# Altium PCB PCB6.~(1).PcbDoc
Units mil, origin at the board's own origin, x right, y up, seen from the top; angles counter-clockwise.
Board outline 6000 x 4000 mil, 2 copper layers (Top Layer, Bottom Layer); 86 components, 57 nets, 223 pads, 27 vias.
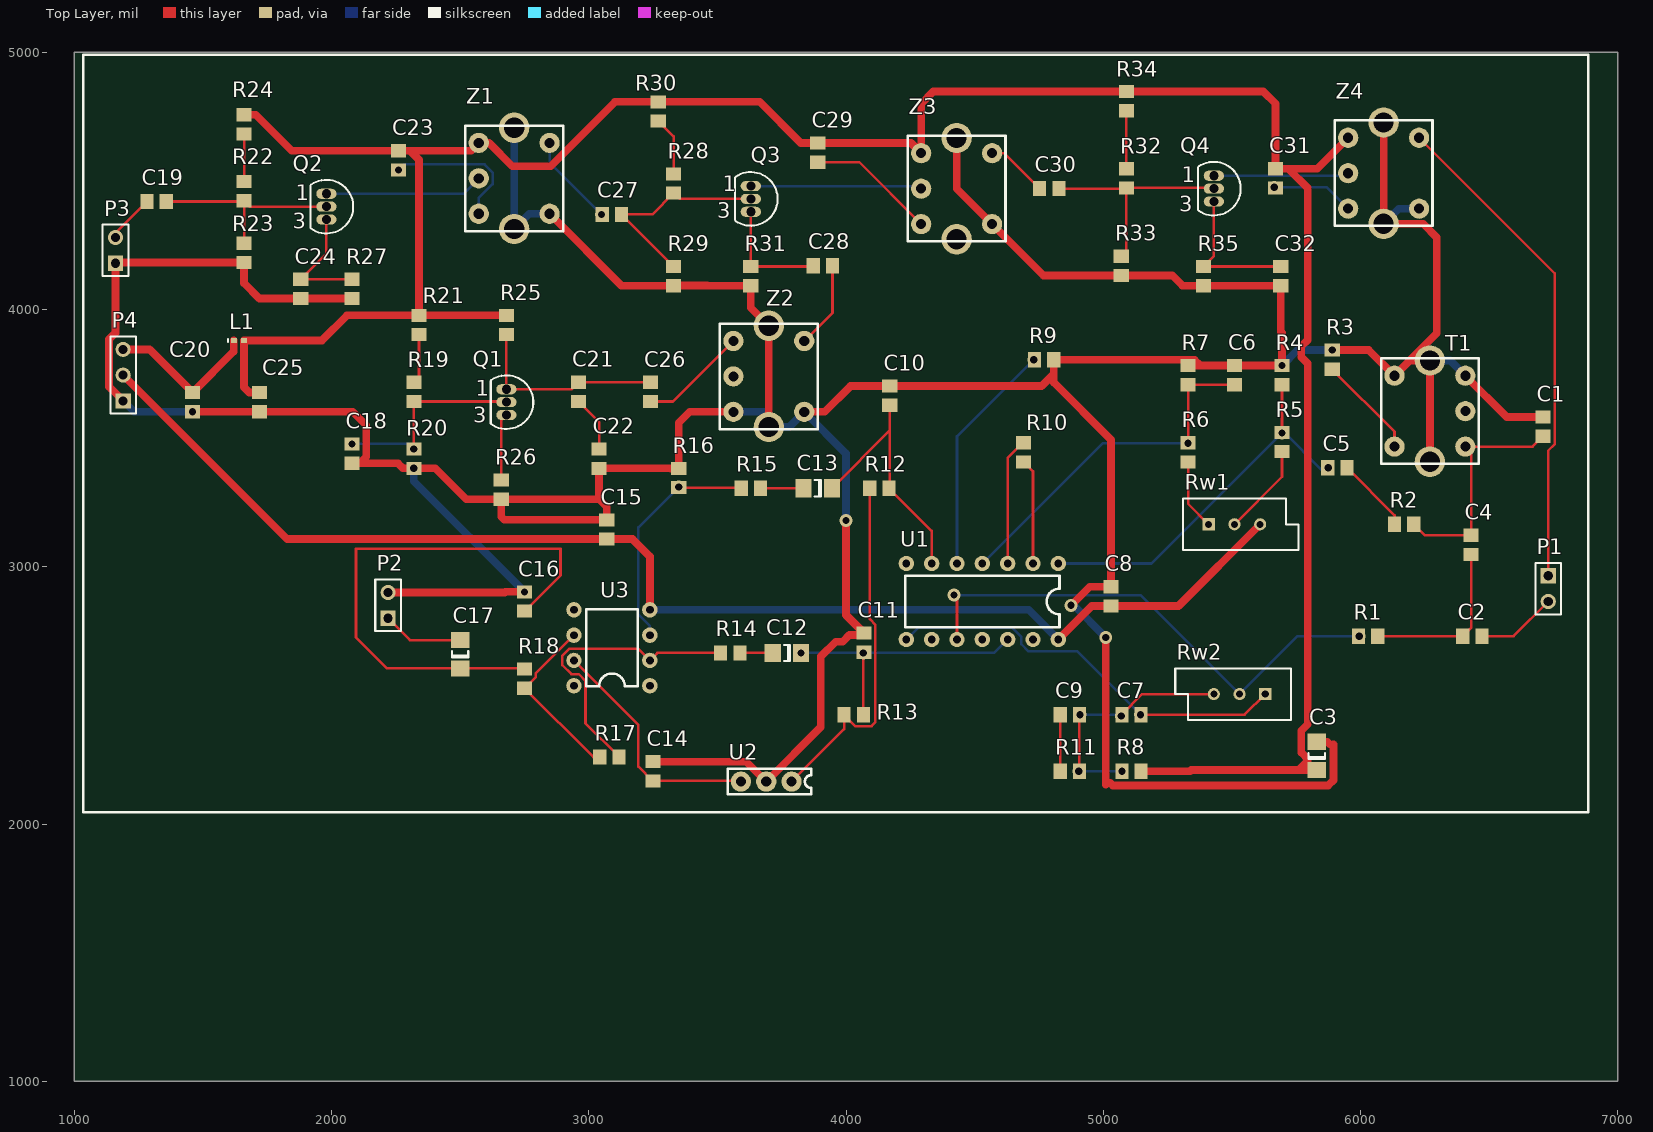
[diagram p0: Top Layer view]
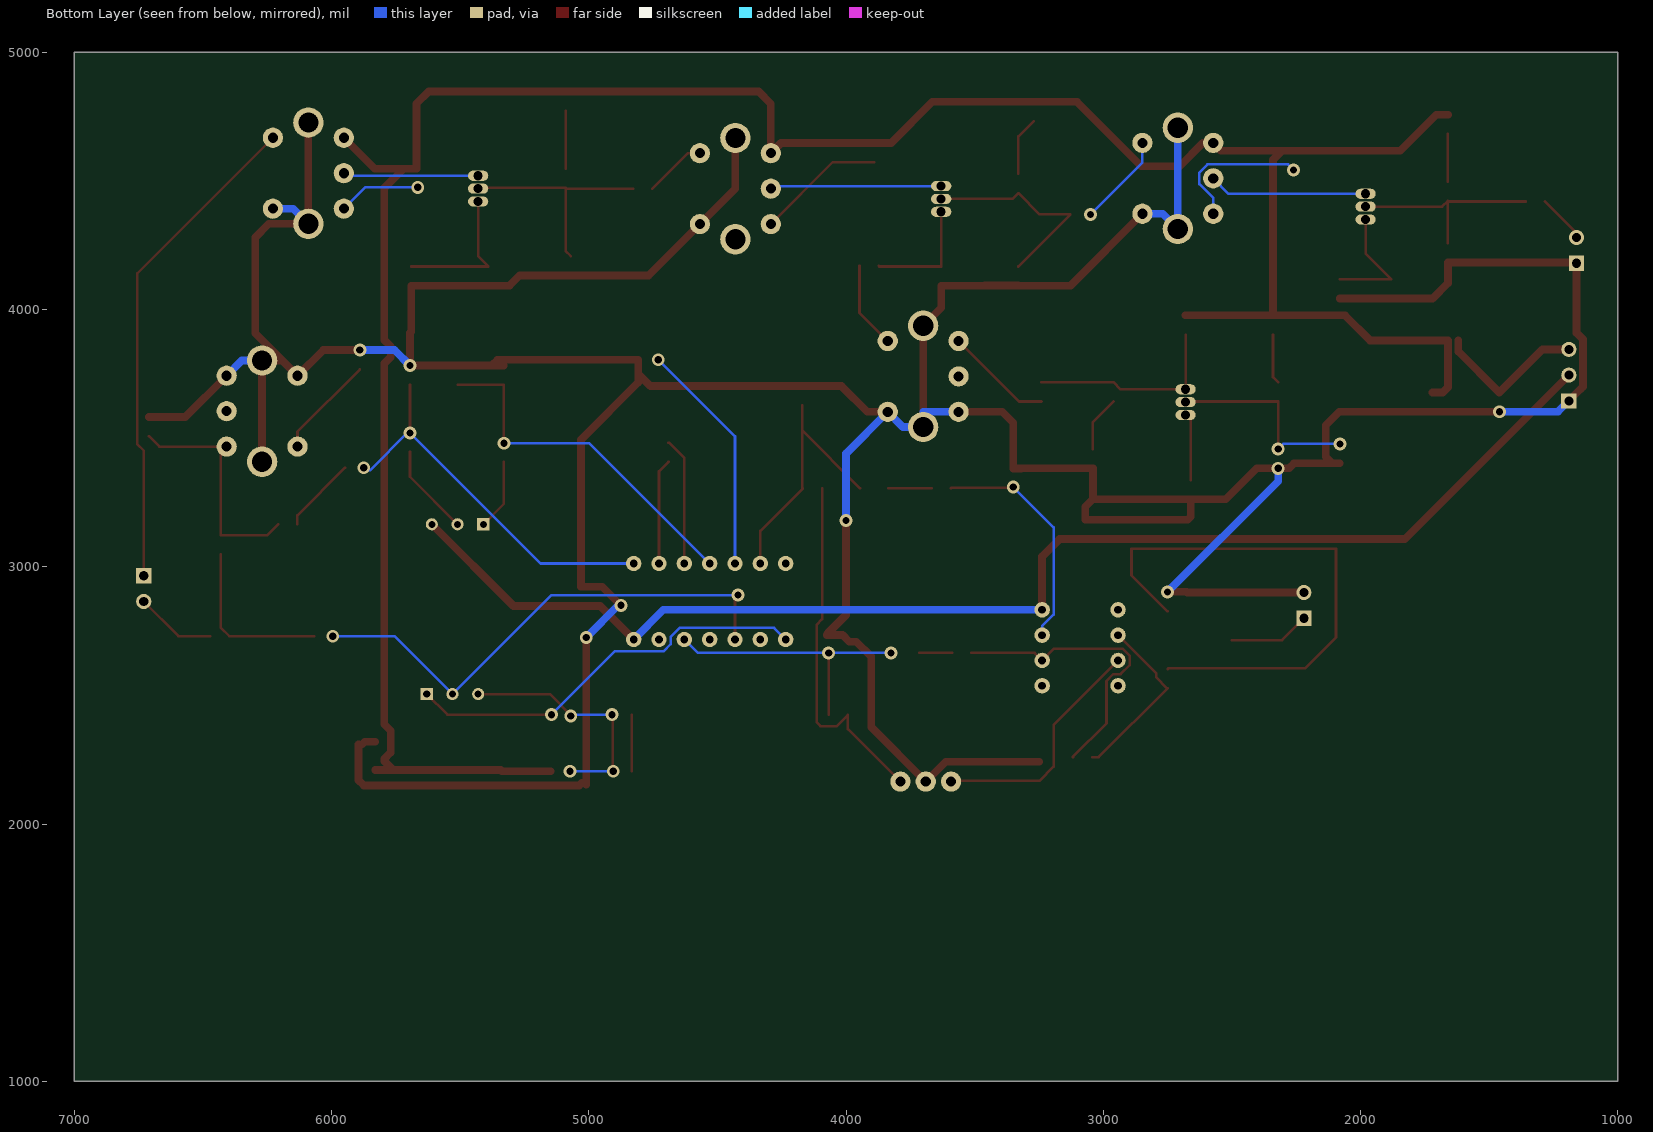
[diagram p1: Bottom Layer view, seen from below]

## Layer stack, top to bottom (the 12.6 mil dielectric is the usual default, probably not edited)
Top Layer: signal copper 1.4
Dielectric: dielectric 12.6, FR-4, Dk 4.8
Bottom Layer: signal copper 1.4

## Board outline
1000,1000 7000,1000 7000,5000 1000,5000

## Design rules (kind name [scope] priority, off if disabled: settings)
Clearance [All] p1: gap=10
PolygonConnect [All] p1: connectstyle=Relief reliefconductorwidth=10 reliefentries=4 polygonreliefangle="90 Angle"
RoutingVias [All] p1: holewidth=28 width=50 viastyle="Through Hole" minholewidth=28 minwidth=50 maxholewidth=28 maxwidth=50
SilkscreenOverComponentPads [All] p1: minsilkscreentomaskgap=10
SolderMaskExpansion [All] p1: expansion=4
TestPointUsage [All] p1: valid=0 allowmultiple=FALSE
Testpoint [All] p1: side=15 testpointundercomponent=TRUE minsize=40 maxsize=100 preferedsize=60 minholesize=0 maxholesize=40 preferedholesize=32 testpointgrid=1 style=1023 order=0123456789
Width [All] p1: maxlimit=100 minlimit=10 preferedwidth=10 minimp=50.000000 maximp=50.000000 favimp=50.000000
23 further rules are at their usual default settings.

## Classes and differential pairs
component class Sheet2: C18 C19 C20 C21 C22 C23 C24 C25 C26 C27 C28 C29 C30 C31 C32 L1 P3 P4 Q1 Q2 Q3 Q4 R19 R20 R21 R22 R23 R24 R25 R26 R27 R28 R29 R30 R31 R32 R33 R34 R35 Z1 Z2 Z3 Z4
component class Sheet1: C1 C2 C3 C4 C5 C6 C7 C8 C9 C10 C11 C12 C13 C14 C15 C16 C17 P1 P2 R1 R2 R3 R4 R5 R6 R7 R8 R9 R10 R11 R12 R13 R14 R15 R16 R17 R18 Rw1 Rw2 T1 U1 U2 U3

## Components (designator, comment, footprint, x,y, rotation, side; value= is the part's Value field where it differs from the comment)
C1 "Cap" 2012[0805] 6710,3545 r270 top
C2 "Cap" 2012[0805] 6435,2730 r180 top
C3 "Cap Pol1" C1206 5830,2265 r90 top
C4 "Cap" 2012[0805] 6430,3085 r270 top
C5 "Cap" 2012[0805] 5910,3385 r180 top
C6 "Cap" 2012[0805] 5510,3745 r270 top
C7 "Cap" 2012[0805] 5110,2425 r180 top
C8 "Cap" 2012[0805] 5030,2885 r270 top
C9 "Cap" 2012[0805] 4870,2425 r180 top
C10 "Cap" 2012[0805] 4170,3665 r270 top
C11 "Cap" 2012[0805] 4070,2705 r270 top
C12 "Cap Pol1" C1206 3770,2665 r180 top
C13 "Cap Pol1" C1206 3890,3305 r180 top
C14 "Cap" 2012[0805] 3250,2205 r270 top
C15 "Cap" 2012[0805] 3070,3145 r270 top
C16 "Cap" 2012[0805] 2750,2865 r270 top
C17 "Cap Pol1" C1206 2500,2660 r90 top
C18 "Cap" 2012[0805] 2080,3440 r270 top
C19 "Cap" 2012[0805] 1320,4420 r0 top
C20 "Cap" 2012[0805] 1460,3640 r90 top
C21 "Cap" 2012[0805] 2960,3680 r270 top
C22 "Cap" 2012[0805] 3040,3420 r270 top
C23 "Cap" 2012[0805] 2260,4580 r270 top
C24 "Cap" 2012[0805] 1880,4080 r90 top
C25 "Cap" 2012[0805] 1720,3640 r90 top
C26 "Cap" 2012[0805] 3240,3680 r90 top
C27 "Cap" 2012[0805] 3090,4370 r0 top
C28 "Cap" 2012[0805] 3910,4170 r0 top
C29 "Cap" 2012[0805] 3890,4610 r270 top
C30 "Cap" 2012[0805] 4790,4470 r0 top
C31 "Cap" 2012[0805] 5670,4510 r270 top
C32 "Cap" 2012[0805] 5690,4130 r90 top
L1 "Inductor" 0402-A 1640,3880 r0 top
P1 "Header 2" HDR1X2 6730,2965 r270 top
P2 "Header 2" HDR1X2 2220,2800 r90 top
P3 "Header 2" HDR1X2 1160,4180 r90 top
P4 "Header 3" HDR1X3 1190,3645 r90 top
Q1 "NPN" TO-226 2680,3640 r180 top
Q2 "NPN" TO-226 1980,4400 r180 top
Q3 "NPN" TO-226 3630,4430 r180 top
Q4 "NPN" TO-226 5430,4470 r180 top
R1 "Res1" 2012[0805] 6030,2730 r180 top
R2 "Res1" 2012[0805] 6170,3165 r180 top
R3 "Res1" 2012[0805] 5890,3805 r270 top
R4 "Res1" 2012[0805] 5695,3745 r270 top
R5 "Res1" 2012[0805] 5695,3485 r270 top
R6 "Res1" 2012[0805] 5330,3445 r270 top
R7 "Res1" 2012[0805] 5330,3745 r270 top
R8 "Res1" 2012[0805] 5110,2205 r180 top
R9 "Res1" 2012[0805] 4770,3805 r180 top
R10 "Res1" 2012[0805] 4690,3445 r270 top
R11 "Res1" 2012[0805] 4870,2205 r180 top
R12 "Res1" 2012[0805] 4130,3305 r180 top
R13 "Res1" 2012[0805] 4030,2425 r180 top
R14 "Res1" 2012[0805] 3550,2665 r180 top
R15 "Res1" 2012[0805] 3630,3305 r180 top
R16 "Res1" 2012[0805] 3350,3345 r270 top
R17 "Res1" 2012[0805] 3080,2260 r180 top
R18 "Res1" 2012[0805] 2750,2565 r270 top
R19 "Res1" 2012[0805] 2320,3680 r90 top
R20 "Res1" 2012[0805] 2320,3420 r90 top
R21 "Res Adj1" 2012[0805] 2340,3940 r270 top
R22 "Res1" 2012[0805] 1660,4460 r90 top
R23 "Res1" 2012[0805] 1660,4220 r90 top
R24 "Res Adj1" 2012[0805] 1660,4720 r270 top
R25 "Res1" 2012[0805] 2680,3940 r90 top
R26 "Res1" 2012[0805] 2660,3300 r90 top
R27 "Res1" 2012[0805] 2080,4080 r90 top
R28 "Res1" 2012[0805] 3330,4490 r90 top
R29 "Res1" 2012[0805] 3330,4130 r90 top
R30 "Res Adj1" 2012[0805] 3270,4770 r270 top
R31 "Res1" 2012[0805] 3630,4130 r90 top
R32 "Res1" 2012[0805] 5090,4510 r90 top
R33 "Res1" 2012[0805] 5070,4170 r90 top
R34 "Res Adj1" 2012[0805] 5090,4810 r270 top
R35 "Res1" 2012[0805] 5390,4130 r90 top
Rw1 "RPot" VR5 5510,3165 r0 top
Rw2 "RPot" VR5 5530,2505 r180 top
T1 "zhongzhou" zhongzhou 6270,3605 r180 top
U1 "MC1496" MC1496 4530,2865 r180 top
U2 "LM7808" LM7808 3690,2165 r180 top
U3 "LM741" LM741 3090,2685 r180 top
Z1 "zhongzhou1" zhongzhou 2710,4510 r0 top
Z2 "zhongzhou4" zhongzhou 3700,3740 r0 top
Z3 "zhongzhou2" zhongzhou 4430,4470 r0 top
Z4 "zhongzhou3" zhongzhou 6090,4530 r0 top

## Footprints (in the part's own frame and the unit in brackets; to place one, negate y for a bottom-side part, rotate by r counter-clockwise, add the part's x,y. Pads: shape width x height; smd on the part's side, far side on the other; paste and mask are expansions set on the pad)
0402-A [mm] "Chip Inductor; Body 1 x 0.5 mm (LxW typ)"
  rect 0.6x0.5 smd: 1(-0.5,0) 2(0.5,0)
  silkscreen extent -1.1,-0.15 -1.1,0.15
2012[0805] [mm] "Chip Resistor; Body 2.0 x 1.3 mm (LxW typ)"
  rect 1.3x1.5 smd: 1(-0.95,0) 2(0.95,0)
C1206 [mm] "Chip Capacitor; Body 3.2 x 1.6 mm (LxW typ)"
  rect 1.6x1.8 smd: 1(-1.4,0) 2(1.4,0)
  silkscreen extent -0.3,-0.8 0.3,0.8
HDR1X2 [mm] "Connector; Header; 2 Position"
  rect 1.5x1.5 hole 0.9: 1(0,0)
  round 1.5 hole 0.9: 2(2.54,0)
  silkscreen extent -1.27,-1.27 3.81,1.27
HDR1X3 [mm] "Connector; Header; 3 Position"
  rect 1.5x1.5 hole 0.9: 1(0,0)
  round 1.5 hole 0.9: 2(2.54,0) 3(5.08,0)
  silkscreen extent -1.27,-1.27 6.35,1.27
LM741 [mil]
  round 60 hole 30: 1(-147.64,147.64) 2(-147.64,49.21) 3(-147.64,-49.21) 4(-147.64,-147.64) 5(147.64,-147.64) 6(147.64,-49.21) 7(147.64,49.21) 8(147.64,147.64)
  silkscreen extent -100,-150 100,150
LM7808 [mm]
  round 2 hole 1: 1(-2.5,0) 2(0,0) 3(2.5,0)
  silkscreen extent -4.44,-1.27 3.81,1.27
MC1496 [mil]
  round 60 hole 30: 1(-295.28,-147.64) 2(-196.85,-147.64) 3(-98.43,-147.64) 4(0,-147.64) 5(98.43,-147.64) 6(196.85,-147.64) 7(295.28,-147.64) 8(295.28,147.64) 9(196.85,147.64) 10(98.43,147.64) 11(0,147.64) 12(-98.43,147.64) 13(-196.85,147.64) 14(-295.28,147.64)
  silkscreen extent -300,-100 300,100
TO-226 [mm] "TO, Flat Index; 3 In-Line, Axial Leads; Body Dia. 4.8mm; Leads 0.55 x 0.51 mm (max)"
  oval 2x1 hole 0.9: 1(0,-1.27) 2(0,0) 3(0,1.27)
  silkscreen extent -2.65,-2.65 1.55,2.65
VR5 [mm] "Potentiometer; 3 Leads"
  rect 1.2x1.2 hole 0.7: 1(-2.54,0)
  round 1.2 hole 0.7: 2(0,0) 3(2.54,0)
  silkscreen extent -5.08,-2.54 6.35,2.54
zhongzhou [mm]
  round 2 hole 1: 1(-3.5,3.5) 2(-3.5,0) 3(-3.5,-3.5) 4(3.5,-3.5) 5(3.5,3.5)
  round 3 hole 2: 6(0,5) 7(0,-5)
  silkscreen extent -4.83,-5.21 4.83,5.21

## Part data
C1 C2 C4 C5 C6 C7 C8 C9 C10 C11 C14 C15 C16 C18 C19 C20 C21 C22 C23 C24 C25 C26 C27 C28 C29 C30 C31 C32: "Capacitor"
C3 C12 C13 C17: "Polarized Capacitor (Radial)"
P1 P2 P3: "Header, 2-Pin"
P4: "Header, 3-Pin"
Q1 Q2 Q3 Q4: "NPN Bipolar Transistor"
R1 R2 R3 R4 R5 R6 R7 R8 R9 R10 R11 R12 R13 R14 R15 R16 R17 R18 R19 R20 R22 R23 R25 R26 R27 R28 R29 R31 R32 R33 R35: "Resistor"
R21 R24 R30 R34: "Variable Resistor"
Rw1 Rw2: "Potentiometer"

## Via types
v1: diameter 50, hole 28, Top Layer to Bottom Layer, 27 vias

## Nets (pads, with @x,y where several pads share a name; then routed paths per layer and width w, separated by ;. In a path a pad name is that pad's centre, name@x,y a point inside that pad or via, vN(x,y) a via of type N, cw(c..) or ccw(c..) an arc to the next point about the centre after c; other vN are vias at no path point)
+12V: C3.1 C23.1 C25.2 C29.1 C31.1 L1.2 R8.1 R21.1 R24.1 R25.2 R30.1 R34.1 Z1.1 Z3.1 Z4.1 | length 10292.6
  Top Layer w30: R24.1 1705,4757.4 1845,4617.4 C23.1 ; C25.2 1680,3677.4 1659.69,3697.72 L1.2 1963,3880 2060.4,3977.4 R21.1 ; R25.2 2680,3978 R21.1@2340,3978 ; R8.1 5337,2205 5341.88,2209.88 5760,2209.88 ; C3.1 5760,2209.88 ; Z4.1 5831.81,4547.4 5720,4547.4 ; C23.1 2305,4617.4 ; C23.1 2305,4617.4 ; 2305,4617.4 2541.81,4617.4 Z1.1 2612,4647.8 2702.8,4557 2852,4557 3102.4,4807.4 R30.1 3664.6,4807.4 3824.6,4647.4 C29.1 4252.6,4647.4 Z3.1 4292.2,4800 4339.61,4847.4 R34.1 5622.6,4847.4 5670,4800 C31.1 ; 2305,4617.4 2340,4582.4 R21.1@2340,3978 ; R21.1 R21.1@2340,3978 ; R21.1 R21.1@2340,3978 ; C31.1 5720,4547.4 ; C31.1 5720,4547.4 ; 5720,4547.4 5795,4472.4 5795,3881.71 5770,3856.71 5770,3815.29 5795,3790.29 5795,2387.4 5769.57,2361.97 5769.57,2278.27 5795,2252.83 5795,2244.88 5760,2209.88
-8V: C8.2 C15.2 P4.2 Rw1.3 U1.14 U3.4 | length 5152.5
  Top Layer w30: P4.2 1827.4,3107.6 C15.2 3170.04,3107.6 3237.64,3040 U3.4 ; U1.14 4955.51,2847.6 C8.2 5292.6,2847.6 Rw1.3
  Bottom Layer w30: U3.4 4710,2832.64 U1.14
GND: C1.1 C3.2 C6.1 C8.1 C10.1 C11.1 C14.1 C15.1 C16.1 C18.2 C20.1 C22.2 C24.1 C25.1 C32.1 P2.2 P3.1 P4.1 R3.1 R4.1 R7.1 R9.1 R16.1 R20.1 R23.1 R26.1 R27.1 R29.1 R31.1 R33.1 R35.1 T1.3 T1.4 T1.6 T1.7 U2.2 Z1.4 Z1.6 Z1.7 Z2.3 Z2.4 Z2.6 Z2.7 Z3.4 Z3.6 Z4.4 Z4.6 Z4.7 | length 21032.9
  Top Layer w30: P4.1 1145,3690 1135,3700 1135,3770 1135,3884 1160,3909 P3.1 1163,4183 1607,4183 1607.4,4182.6 R23.1 1660,4102.6 1720,4042.6 C24.1 1880,4043 2028,4043 2028.4,4042.6 R27.1 ; v1(1460,3602.6) C25.1 2082.4,3602.6 2135,3550 2135,3427.6 2110,3402.6 ; P2.2 2673,2900 2675.4,2902.4 2720,2902.4 ; Z1.4 3127.4,4092.6 R29.1 3330,4093 3461,4093 3461.4,4092.6 R31.1 3630,4006.85 Z2.6 Z2.7 ; C14.1 3612.6,2242.4 U2.2 3902,2377 3902,2651 3960,2709 3987.5,2709 4013.5,2735 C11.1@4075,2735 ; Z2.3 3392.2,3602.2 3350,3560 R16.1 3319,3382.4 3318.4,3383 3105,3383 3104.6,3382.6 C22.2 3040,3263 3040.4,3262.6 ; Z2.4 3917.2,3602.2 4017.4,3702.4 4137.4,3702.4 ; v1@4000,3185 v1(4000,3180) 4000,2812.4 C11.1 ; Z3.6 4430,4470 Z3.4 4767.4,4132.6 R33.1 5268.4,4132.6 5308.4,4092.6 R35.1 C32.1 5690,3914 5695,3909 5695,3836 ; v1(4875,2850) 4947.4,2922.4 C8.1 5030,3494 4807.4,3716.6 4807.4,3749.8 ; 5010,2153 v1(5010,2725) ; 5027,2160 5037,2150 5875,2150 5895,2170 5895,2309 ; C3.2 5870.88,2320.12 5881,2310 ; v1(5890,3842.4) 6032.6,3842.4 T1.4 ; Z4.6 Z4.7 6243.85,4333.15 6297,4280 6297,3907.59 6230.63,3841.22 6191.26,3801.85 ; T1.6 T1.7 6191.26,3801.85 ; T1.3 6568.19,3582.4 C1.1 ; 2110,3402.6 2258,3402.6 2278,3382.6 v1(2320,3382.6) 2403.4,3382.6 2523.4,3262.6 R26.1 ; 2110,3402.6 C18.2 2110,3402.6 ; R26.1 3040.4,3262.6 ; R26.1 2660,3195 2672.6,3182.4 C15.1 3070,3233 3040.4,3262.6 ; 2720,2902.4 v1(2750,2902.4) 2720,2902.4 ; 4137.4,3702.4 C10.1 ; 4137.4,3702.4 C10.1 ; C10.1 4760,3702.4 4807.4,3749.8 ; 4807.4,3749.8 R9.1 5330,3805 5354.4,3805 5377,3782.4 ; 5377,3782.4 C6.1 v1(5695,3782.4) ; 5377,3782.4 R7.1 5377,3782.4 ; v1(5695,3782.4) 5695,3836 ; v1(5695,3782.4) 5695,3836 ; T1.4 6191.26,3801.85 ; T1.4 6191.26,3801.85
  Bottom Layer w30: P4.1 1232.4,3602.6 v1(1460,3602.6) ; v1(2320,3382.6) 2320,3332.4 v1(2750,2902.4) ; Z1.6 Z1.7 2769.05,4372.2 Z1.4 ; Z2.3 3563,3603 3700,3603 Z2.7 3778.74,3543.15 Z2.4 4000,3440 v1(4000,3180) ; v1(4875,2850) 4885,2850 v1(5010,2725) ; v1(5695,3782.4) 5755,3842.4 v1(5890,3842.4) ; Z4.7 6149.05,4392.2 Z4.4 ; T1.7 6348.74,3801.85 T1.3
NetC1_2: C1.2 C4.1 R2.1 T1.1 | length 913.2
  Top Layer w10: R2.1 6250,3122.4 C4.1 6430,3445 T1.1 6669.61,3467.2 C1.2
NetC2_1: C2.1 P1.2 | length 313.5
  Top Layer w10: C2.1 6595,2730 P1.2
NetC2_2: C2.2 C4.2 R1.1 | length 661.2
  Top Layer w10: R1.1 C2.2 6430,2762.4 C4.2
NetC5_1: C5.1 R2.2 | length 296.7
  Top Layer w10: C5.1 6132.6,3199.8 R2.2
NetC5_2: C5.2 R4.2 R5.1 U1.1 | length 1513.4
  Top Layer w10: R5.1 R4.2
  Bottom Layer w10: U1.1 5187.64,3012.64 5700,3525 5850,3375 5865,3375 v1(5875,3385)
  other v1: 5695,3520
NetC6_2: C6.2 R6.1 R7.2 U1.4 | length 1398.8
  Top Layer w10: R6.1 R7.2 C6.2
  Bottom Layer w10: U1.4 4997.36,3480 v1(5330,3480)
NetC7_1: C7.1 Rw2.1 U1.8 | length 1601.3
  Top Layer w10: C7.1 5550,2425 Rw2.1
  Bottom Layer w10: U1.8 4279.72,2762.36 4647.07,2762.36 4681.85,2727.58 4681.85,2698.72 4708.21,2672.36 4897.64,2672.36 v1(5145,2425)
NetC7_2: C7.2 C9.1 R8.2 R11.1 Rw2.3 | length 948.5
  Top Layer w10: R11.1 C9.1 ; C7.2 5072.6,2426.53 5151.07,2505 Rw2.3
  Bottom Layer w10: v1(4905,2205) v1@5080,2205 ; v1(4910,2425) 5065,2425 v1(5070,2420)
  other v1: 5072.6,2205
NetC9_2: C9.2 R11.2 | length 220
  Top Layer w10: R11.2 C9.2
NetC10_2: C10.2 C13.1 R12.1 U1.6 | length 1002.7
  Top Layer w10: C13.1 4170,3529.88 ; C10.2 4170,3529.88 ; U1.6 4333.15,3139.25 R12.1 4170,3307.6 4170,3529.88
NetC11_2: C11.2 C12.1 R13.1 U1.12 | length 1068.7
  Top Layer w10: R13.1 v1(4067.4,2665) C11.2
  Bottom Layer w10: v1(3825.12,2665) v1(4067.4,2665) 4576.06,2665 U1.12
NetC12_2: C12.2 R14.1 | length 127.5
  Top Layer w10: R14.1 C12.2
NetC13_2: C13.2 R15.1 | length 167.5
  Top Layer w10: R15.1 C13.2
NetC14_2: C14.2 U2.3 U3.7 | length 935.5
  Top Layer w10: U3.7 3192.64,2385.51 3192.64,2223.43 3248.47,2167.6 C14.2 U2.3@3588.98,2167.6
NetC16_2: C16.2 C17.1 R18.1 | length 2147.1
  Top Layer w10: R18.1 2747.52,2604.88 C17.1 2215.12,2604.88 2095,2725 2095,3070 2890,3070 2890,2966.07 2751.53,2827.6 C16.2
NetC17_2: C17.2 P2.1 | length 315.2
  Top Layer w10: P2.1 2304.88,2715.12 C17.2
NetC18_1: C18.1 Q1.2 R19.1 R20.2 | length 794.6
  Top Layer w10: v1(2320,3457.4) R19.1 2677.4,3642.6 Q1.2
  Bottom Layer w10: v1(2080,3477.4) 2300,3477.4 v1(2320,3457.4)
NetC19_1: C19.1 P3.2 | length 190.8
  Top Layer w10: P3.2 1160,4297.4 C19.1
NetC19_2: C19.2 Q2.2 R22.1 R23.2 | length 798.2
  Top Layer w10: C19.2 1657.4,4420 R22.1 ; R23.2 R22.1 ; Q2.2 1682.6,4400 R22.1
NetC20_2: C20.2 L1.1 P4.3 | length 608.2
  Top Layer w30: P4.3 1292.4,3845 C20.2 1619.69,3837.09 L1.1@1619.69,3880
NetC21_1: C21.1 C26.2 Q1.1 R25.1 | length 783.9
  Top Layer w10: R25.1 Q1.1 2932.6,3690 C21.1 C26.2
NetC21_2: C21.2 C22.1 | length 218.3
  Top Layer w10: C21.2 3040,3562.6 C22.1
NetC23_2: C23.2 Z1.3 | length 571.6
  Bottom Layer w10: v1(2260,4542.6) 2281.77,4564.37 2594.72,4564.37 2626.57,4532.52 2626.57,4487.48 2572.2,4433.11 Z1.3
NetC24_2: C24.2 Q2.3 R27.2 | length 474
  Top Layer w10: Q2.3 1980,4217.4 C24.2 R27.2
NetC26_1: C26.1 Z2.1 | length 419.6
  Top Layer w10: C26.1 3327.01,3642.6 Z2.1
NetC27_1: C27.1 Z1.5 | length 361.6
  Bottom Layer w10: Z1.5 2847.8,4572.2 v1(3050,4370)
NetC27_2: C27.2 Q3.2 R28.1 R29.2 | length 832.7
  Top Layer w10: R29.2 C27.2 3247.4,4370 R28.1 3352.6,4430 Q3.2
NetC28_1: C28.1 Q3.3 R31.2 | length 456.3
  Top Layer w10: Q3.3 R31.2 3870,4167.4 C28.1
NetC28_2: C28.2 Z2.5 | length 337.6
  Top Layer w10: Z2.5 3947.4,3987.4 C28.2
NetC29_2: C29.2 Z3.3 | length 501.8
  Top Layer w10: C29.2 4051.81,4572.6 Z3.3
NetC30_1: C30.1 Z3.5 | length 241.9
  Top Layer w10: Z3.5 4614.8,4607.8 C30.1
NetC30_2: C30.2 Q4.2 R32.1 R33.2 | length 878.2
  Top Layer w10: C30.2 5087.4,4470 R32.1 ; R33.2 5090,4227.4 R32.1 ; Q4.2 5427.4,4472.6 R32.1
NetC31_2: C31.2 Z4.3 | length 321.5
  Bottom Layer w10: v1(5665,4475) 5869.41,4475 Z4.3
NetC32_2: C32.2 Q4.3 R35.2 | length 569.2
  Top Layer w10: Q4.3 5430,4207.4 R35.2 C32.2
NetQ1_3: Q1.3 R26.2 | length 260.9
  Top Layer w10: R26.2 2660,3570 Q1.3
NetQ2_1: Q2.1 Z1.2 | length 617.1
  Bottom Layer w10: Q2.1 2512.2,4450 Z1.2
NetQ3_1: Q3.1 Z3.2 | length 666.3
  Bottom Layer w10: Q3.1 4282.2,4480 Z3.2
NetQ4_1: Q4.1 Z4.2 | length 526.3
  Bottom Layer w10: Q4.1 5942.2,4520 Z4.2
NetR1_2: R1.2 Rw2.2 U1.10 | length 2005.1
  Top Layer w10: v1(4420,2890) 4431.57,2878.43 U1.10
  Bottom Layer w10: v1(4420,2890) 5145,2890 Rw2.2 5755,2730 v1(5995,2730)
NetR3_2: R3.2 T1.5 | length 400.7
  Top Layer w10: R3.2 6132.2,3525.39 T1.5
NetR5_2: R5.2 Rw1.2 | length 359.2
  Top Layer w10: Rw1.2 5695,3350 R5.2
NetR6_2: R6.2 Rw1.1 | length 275.7
  Top Layer w10: R6.2 5330,3245 Rw1.1
NetR9_2: R9.2 U1.5 | length 916
  Bottom Layer w10: U1.5 4431.57,3506.57 v1(4730,3805)
NetR10_1: R10.1 U1.3 | length 496.2
  Top Layer w10: U1.3 4628.43,3422.36 4688.47,3482.4 R10.1
NetR10_2: R10.2 U1.2 | length 410.2
  Top Layer w10: R10.2 4726.85,3370.75 U1.2
NetR12_2: R12.2 R13.2 U2.1 | length 1408.9
  Top Layer w10: U2.1 3992.6,2369.17 R13.2@3992.6,2423.47 ; R13.2 R13.2@3992.6,2423.47 ; R12.2 4092.6,2796.14 4114.53,2774.21 4114.53,2395.79 4099.21,2380.47 4035.6,2380.47 R13.2@3992.6,2423.47
NetR14_2: R14.2 R17.1 U3.2 | length 1159.4
  Top Layer w10: R17.1 3117.4,2261.53 2987.36,2391.57 2987.36,2556 2961,2582.36 2932.15,2582.36 2897.36,2617.15 2897.36,2654.43 2923.72,2680.79 3192.64,2680.79 U3.2 3266.85,2665 R14.2
NetR15_2: R15.2 R16.2 U3.3 | length 903.3
  Top Layer w10: R16.2 3590,3307.6 R15.2
  Bottom Layer w10: U3.3 3237.64,2769 3192.64,2814 3192.64,3152.64 v1(3350,3310)
NetR17_2: R17.2 R18.2 U3.6 | length 690.6
  Top Layer w10: U3.6 2794.53,2586.38 2794.53,2570.6 2751.53,2527.6 R18.2 3017.6,2260 R17.2
NetR19_2: R19.2 R21.2 | length 193.5
  Top Layer w10: R19.2 2340,3737.4 R21.2
NetR22_2: R22.2 R24.2 | length 185.2
  Top Layer w10: R22.2 R24.2
NetR28_2: R28.2 R30.2 | length 230
  Top Layer w10: R30.2 3330,4672.6 R28.2
NetR32_2: R32.2 R34.2 | length 225.2
  Top Layer w10: R32.2 R34.2
ZHONGFANG: P1.1 Z4.5 | length 1931.1
  Top Layer w10: Z4.5 6754.53,4141.06 6754.53,3475.79 6730,3451.27 P1.1
pads on no net: T1.2 U1.7 U1.9 U1.11 U1.13 U3.1 U3.5 U3.8 Z2.2 Z3.7

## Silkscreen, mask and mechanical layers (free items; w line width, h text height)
Top Overlay:
  lines w10: 1035,2045 1035,4880 1035,4905 1035,4965 1035,4990 6885,4990 6885,2045 1035,2045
